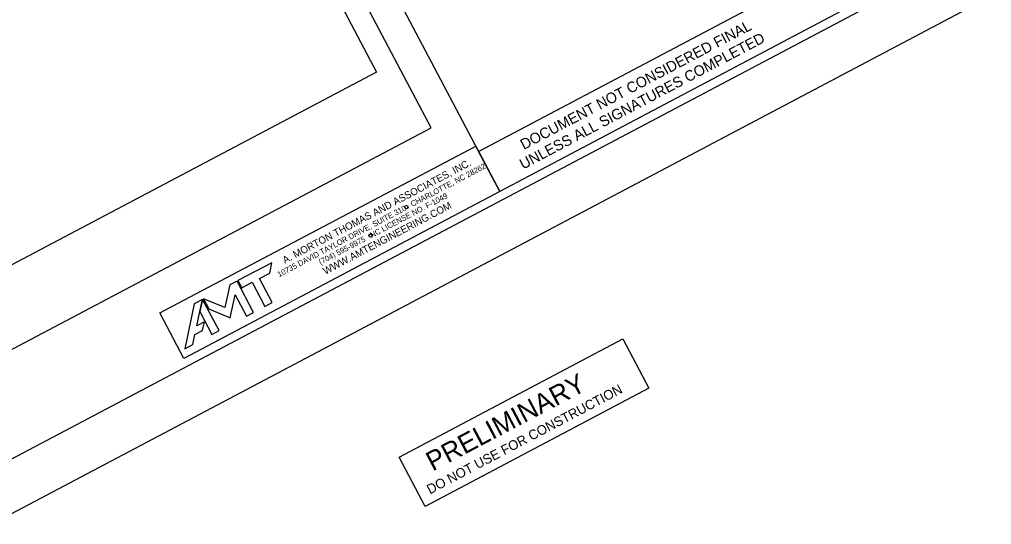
# Model space of a CAD drawing. Extents: x 1485914 to 1489436, y 493744 to 499689.
# Drawn here: x 1488661 to 1489164, y 498298 to 498560 of the extents above; entities that cross this region are included whole.
import ezdxf

# ---------------------------------------------------------------- set-up
doc = ezdxf.new("R2010")
doc.units = 0
for name, color, linetype in [('DEV BORDER CELL', 7, 'Continuous'), ('DEV PRELIMINARY STAMP CELL', 7, 'Continuous'), ('Gray Area Fill Shapes', 7, 'Continuous'), ('Prop Grid Mask', 7, 'Continuous'), ('Scratch_Level_0', 7, 'Continuous'), ('Sheet Block Title CELL', 7, 'Continuous'), ('Sheet Plot Border Outside CELL', 7, 'Continuous'), ('Sheet Sticker Exception Certification CELL', 7, 'Continuous'), ('WZ OSDR CELL', 7, 'Continuous')]:
    doc.layers.add(name, color=color, linetype=linetype)

msp = doc.modelspace()

# ---------------------------------------------------------------- linework, layer by layer
at = {"layer": 'DEV BORDER CELL'}
for points in [[(1488911.97, 499654.77), (1487585.52, 498954.38), (1488075.8, 498025.87), (1489402.24, 498726.26)], [(1488845.1, 498592.4), (1489021.99, 498685.8), (1489086.19, 498564.21), (1488909.3, 498470.8)]]:
    msp.add_lwpolyline(points, close=True, dxfattribs=at)
at = {"layer": 'DEV PRELIMINARY STAMP CELL'}
msp.add_lwpolyline([(1488857.2, 498333.36), (1488973.05, 498394.53), (1488986.55, 498368.97), (1488870.69, 498307.8)], close=True, dxfattribs=at)
msp.add_lwpolyline([(1488857.2, 498333.36), (1488973.05, 498394.53), (1488986.55, 498368.97), (1488870.69, 498307.8)], close=True, dxfattribs=at)
at = {"layer": 'Gray Area Fill Shapes'}
msp.add_lwpolyline([(1488857.2, 498333.36), (1488973.05, 498394.53), (1488986.55, 498368.97), (1488870.69, 498307.8)], close=True, dxfattribs=at)
at = {"layer": 'Prop Grid Mask'}
msp.add_lwpolyline([(1488733.25, 498407.96), (1488896.87, 498494.35), (1488909.3, 498470.8), (1488745.68, 498384.41)], close=True, dxfattribs=at)
at = {"layer": 'Scratch_Level_0'}
msp.add_lwpolyline([(1488891.1, 499587.21), (1487653.08, 498933.51), (1488096.67, 498093.43), (1488873.83, 498503.79), (1488818.61, 498608.38), (1489279.46, 498851.72)], close=True, dxfattribs=at)
at = {"layer": 'Sheet Block Title CELL'}
msp.add_lwpolyline([(1488733.25, 498407.96), (1488896.87, 498494.35), (1488909.3, 498470.8), (1488745.68, 498384.41)], close=True, dxfattribs=at)
for points in [[(1488791.41, 498413.31), (1488784.83, 498425.78), (1488790.2, 498428.61), (1488791.34, 498433.96), (1488773.74, 498424.67), (1488775.7, 498420.96), (1488781.12, 498423.82), (1488787.7, 498411.35), (1488791.41, 498413.31)], [(1488769.72, 498405.5), (1488772.27, 498417.32), (1488778.1, 498406.28), (1488781.81, 498408.24), (1488773.27, 498424.42), (1488769.56, 498422.46), (1488766.95, 498410.75), (1488755.89, 498415.24), (1488758.61, 498410.09), (1488769.72, 498405.5)], [(1488754, 498408.68), (1488755.41, 498414.99), (1488751.08, 498412.7), (1488746.19, 498389.43), (1488750.39, 498391.65), (1488751.48, 498396.87), (1488755.33, 498398.9), (1488756.35, 498403.36), (1488752.37, 498401.26), (1488754, 498408.68)], [(1488763.95, 498398.81), (1488755.41, 498414.99), (1488754, 498408.68), (1488760.24, 498396.85), (1488763.95, 498398.81)]]:
    msp.add_lwpolyline(points, dxfattribs=at)
for centre in [(1488860.97, 498462.74), (1488842.43, 498448.03)]:
    msp.add_circle(centre, 0.833, dxfattribs=at)
at = {"layer": 'Sheet Plot Border Outside CELL'}
msp.add_lwpolyline([(1487943.33, 497927.66), (1489436.02, 498715.83), (1488922.4, 499688.55), (1487429.71, 498900.38)], close=True, dxfattribs=at)
at = {"layer": 'Sheet Sticker Exception Certification CELL'}
for p, q in [((1488898.33, 498491.59), (1489075.22, 498584.99)), ((1489086.19, 498564.21), (1488909.3, 498470.8)), ((1488909.3, 498470.8), (1488898.33, 498491.59))]:
    msp.add_line(p, q, dxfattribs=at)
at = {"layer": 'WZ OSDR CELL'}
msp.add_lwpolyline([(1487648.11, 498943.96), (1488414.63, 499348.7), (1488845.5, 498532.69), (1488078.98, 498127.95)], close=True, dxfattribs=at)

# ---------------------------------------------------------------- texts
at = {"layer": 'DEV PRELIMINARY STAMP CELL'}
for s, height, p in [(' PRELIMINARY', 9.9999, (1488871.27, 498324.11)), ('DO NOT USE FOR CONSTRUCTION', 5.0001, (1488873.18, 498313.95))]:
    msp.add_text(s, height=height, rotation=27.8351, dxfattribs=at).set_placement(p)
at = {"layer": 'Sheet Block Title CELL'}
for s, height, p in [('A. MORTON THOMAS AND ASSOCIATES, INC.', 3.75, (1488798.05, 498433.36)), ('10735 DAVID TAYLOR DRIVE, SUITE 310   CHARLOTTE, NC 28262', 2.9167, (1488795.06, 498426.36)), ('(704) 595-9975   NC LICENSE NO. F-1049', 2.9167, (1488816.55, 498432.76)), ('WWW.AMTENGINEERING.COM', 3.75, (1488818.98, 498427.69))]:
    msp.add_text(s, height=height, rotation=27.8346, dxfattribs=at).set_placement(p)
at = {"layer": 'Sheet Sticker Exception Certification CELL'}
for s, p in [('DOCUMENT NOT CONSIDERED FINAL', (1488921.79, 498492.28)), ('UNLESS ALL SIGNATURES COMPLETED', (1488921.42, 498482.13))]:
    msp.add_text(s, height=5.5, rotation=27.8351, dxfattribs=at).set_placement(p)

doc.saveas('drawing.dxf')
